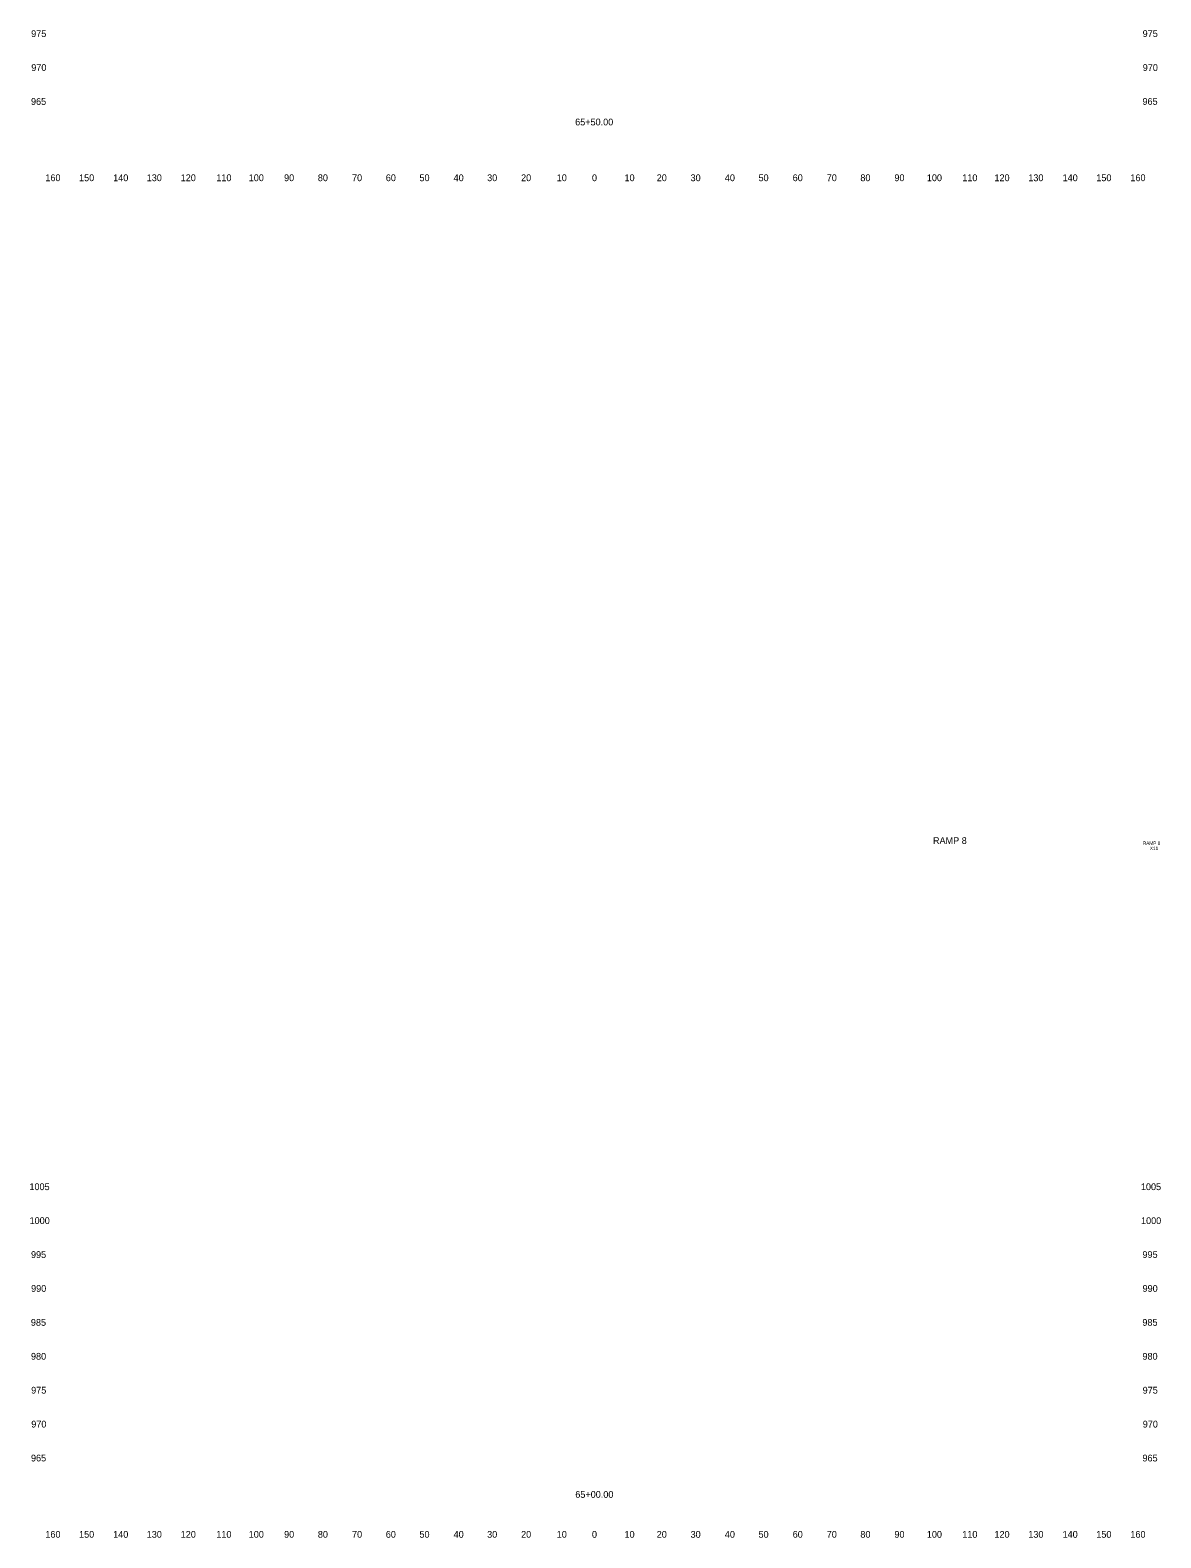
# Model space of a CAD drawing. Extents: x 4994 to 5843, y 4997 to 8804.
# Drawn here: x 5508.6 to 5842.1, y 4997.5 to 5442 of the extents above; entities that cross this region are included whole.
import ezdxf

# ---------------------------------------------------------------- set-up
doc = ezdxf.new("R2010")
doc.units = 0
for name, color, linetype in [('RD_SHT_ID', 7, 'Continuous'), ('RD_XS_TX_Offset', 7, 'Continuous'), ('RD_XS_TX_Station', 7, 'Continuous')]:
    doc.layers.add(name, color=color, linetype=linetype)

msp = doc.modelspace()

# ---------------------------------------------------------------- texts
at = {"layer": 'RD_SHT_ID'}
for s, height, p in [('RAMP 8', 2, (5774.88, 5202.06)), ('RAMP 8', 1, (5836.78, 5201.8)), ('X11', 1, (5838.85, 5200.3))]:
    msp.add_text(s, height=height, dxfattribs=at).set_placement(p)
at = {"layer": 'RD_XS_TX_Offset'}
for s, p in [('975', (5508.91, 5440)), ('975', (5836.71, 5440)), ('970', (5508.94, 5430)), ('970', (5836.74, 5430)), ('965', (5508.86, 5420)), ('965', (5836.66, 5420)), ('160', (5513.1, 5397.5)), ('150', (5523.04, 5397.5)), ('140', (5533.1, 5397.5)), ('130', (5542.99, 5397.5)), ('120', (5553.01, 5397.5)), ('110', (5563.51, 5397.5)), ('100', (5573.07, 5397.5)), ('90', (5583.5, 5397.5)), ('80', (5593.46, 5397.5)), ('70', (5603.54, 5397.5)), ('60', (5613.5, 5397.5)), ('50', (5623.43, 5397.5)), ('40', (5633.5, 5397.5)), ('30', (5643.39, 5397.5)), ('20', (5653.4, 5397.5)), ('10', (5663.91, 5397.5)), ('0', (5674.3, 5397.5)), ('0', (5674.3, 5397.5)), ('10', (5683.91, 5397.5)), ('20', (5693.4, 5397.5)), ('30', (5703.39, 5397.5)), ('40', (5713.5, 5397.5)), ('50', (5723.43, 5397.5)), ('60', (5733.5, 5397.5)), ('70', (5743.54, 5397.5)), ('80', (5753.46, 5397.5)), ('90', (5763.5, 5397.5)), ('100', (5773.07, 5397.5)), ('110', (5783.51, 5397.5)), ('120', (5793.01, 5397.5)), ('130', (5802.99, 5397.5)), ('140', (5813.1, 5397.5)), ('150', (5823.04, 5397.5)), ('160', (5833.1, 5397.5)), ('1005', (5508.4, 5100)), ('1005', (5836.2, 5100)), ('1000', (5508.44, 5090)), ('1000', (5836.24, 5090)), ('995', (5508.86, 5080)), ('995', (5836.66, 5080)), ('990', (5508.89, 5070)), ('990', (5836.69, 5070)), ('985', (5508.83, 5060)), ('985', (5836.63, 5060)), ('980', (5508.86, 5050)), ('980', (5836.66, 5050)), ('975', (5508.91, 5040)), ('975', (5836.71, 5040)), ('970', (5508.94, 5030)), ('970', (5836.74, 5030)), ('965', (5508.86, 5020)), ('965', (5836.66, 5020)), ('160', (5513.1, 4997.5)), ('150', (5523.04, 4997.5)), ('140', (5533.1, 4997.5)), ('130', (5542.99, 4997.5)), ('120', (5553.01, 4997.5)), ('110', (5563.51, 4997.5)), ('100', (5573.07, 4997.5)), ('90', (5583.5, 4997.5)), ('80', (5593.46, 4997.5)), ('70', (5603.54, 4997.5)), ('60', (5613.5, 4997.5)), ('50', (5623.43, 4997.5)), ('40', (5633.5, 4997.5)), ('30', (5643.39, 4997.5)), ('20', (5653.4, 4997.5)), ('10', (5663.91, 4997.5)), ('0', (5674.3, 4997.5)), ('0', (5674.3, 4997.5)), ('10', (5683.91, 4997.5)), ('20', (5693.4, 4997.5)), ('30', (5703.39, 4997.5)), ('40', (5713.5, 4997.5)), ('50', (5723.43, 4997.5)), ('60', (5733.5, 4997.5)), ('70', (5743.54, 4997.5)), ('80', (5753.46, 4997.5)), ('90', (5763.5, 4997.5)), ('100', (5773.07, 4997.5)), ('110', (5783.51, 4997.5)), ('120', (5793.01, 4997.5)), ('130', (5802.99, 4997.5)), ('140', (5813.1, 4997.5)), ('150', (5823.04, 4997.5)), ('160', (5833.1, 4997.5))]:
    msp.add_text(s, height=2, dxfattribs=at).set_placement(p)
at = {"layer": 'RD_XS_TX_Station'}
for s, p in [('65+50.00', (5669.35, 5413.95)), ('65+00.00', (5669.39, 5009.27))]:
    msp.add_text(s, height=2, dxfattribs=at).set_placement(p)

doc.saveas('drawing.dxf')
